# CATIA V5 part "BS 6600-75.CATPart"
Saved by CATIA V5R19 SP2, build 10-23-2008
Part number: BS 6600-75
Bounding box of the stored display mesh (mm): x -59.975 to 59.975, y -59.975 to 59.975, z 0 to 225
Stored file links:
  C:\Users\Bora\Desktop\3D Katı model\BS serisi\BS 6600\BS 6600-75.CATPart
  C:\Program Files\Dassault Systemes\B19\intel_a\reffiles\standard\MetricThickPitch.txt
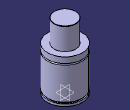
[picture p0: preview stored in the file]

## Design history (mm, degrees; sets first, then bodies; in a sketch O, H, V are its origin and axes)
Body1 (main body)
  Sketch1 on yz-plane, origin (0, 0, 0), H (0, 1, 0), V (0, 0, 1)
    point P1 (60, 129)
    point P2 (60, 124)
    point P3 (60, 129)
    point P7 (37.5, 224)
    point P9 (37.5, 224)
    point P14 (60, 124)
    arc A1 centre (60, 126.5) radius 2.5 from (60, 129) to (60, 124) ccw
    line L1 (60, 129) -> (60, 149)
    line L2 (60, 0) -> (60, 8)
    arc A2 centre (36.5, 224) radius 1 from (37.5, 224) to (36.5, 225) ccw
    line L3 (37.5, 224) -> (37.5, 149)
    line L4 (56, 13) -> (56, 8)
    line L5 (60, 13) -> (60, 124)
    line L6 (36.5, 225) -> (0, 225)
    point P15 (0, 225)
    line L7 (60, 149) -> (37.5, 149)
    line L8 (0, 0) -> (60, 0)
    line L9 (56, 13) -> (60, 13)
    line L10 (56, 8) -> (60, 8)
    coincidence: P15 V, P1 P3, P2 P14, P7 P9
    tangency: L6 A2
    horizontal: L7 H, L8 H, L9 H, L10 H
  Shaft1: profile Sketch1, axis Sketch1.V, angle 360
  Sketch2 on face of Shaft1 from Sketch1.L8, origin (0, 0, 0), H (1, 0, 0), V (0, -1, 0)
    point P1 (40, 0)
    distance P1 V = 40
  Hole1: placed by Sketch2, at (40, 0, 0) direction (0, 0, 1), diameter 8.376, depth 8, threaded "M10", thread diameter 10, thread depth 8, pitch 1.5
  CircPattern1: of Hole1, instances 4, angular step 90, axis from xy-plane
